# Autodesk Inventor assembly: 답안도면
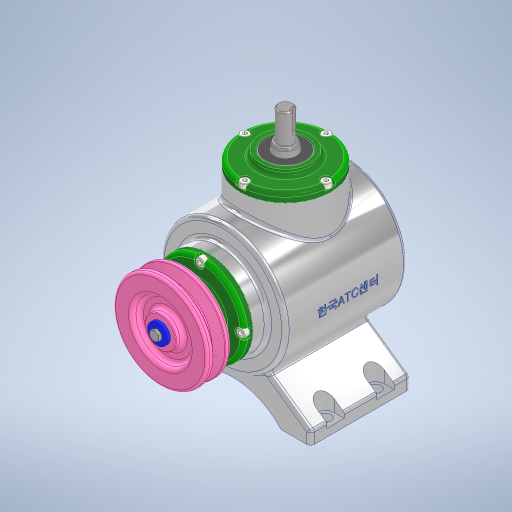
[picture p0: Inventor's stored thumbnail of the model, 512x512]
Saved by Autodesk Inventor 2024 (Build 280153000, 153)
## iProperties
Created: 2023-08
Part Number: 답안도면
Document SubType Name: Assembly
Designer: Owner
Author: Owner
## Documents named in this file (17)
- C:\Users\Owner\Desktop\730813V1006\답안조립품.iam
- C:\Users\Owner\Desktop\730813V1006\본체.ipt
- C:\Users\Owner\Desktop\730813V1006\V-벨트풀리.ipt
- C:\Users\Owner\Desktop\730813V1006\메인 베벨기어.ipt
- C:\Users\Owner\Desktop\730813V1006\메인 축.ipt
- 메인 축.ipt
- C:\Users\Owner\Desktop\730813V1006\베어링 6203.ipt
- C:\Users\Owner\Desktop\730813V1006\볼트 M4 x 10.ipt
- C:\Users\Owner\Desktop\730813V1006\서브 베벨기어.ipt
- C:\Users\Owner\Desktop\730813V1006\서브 축.ipt
- 서브 축.ipt
- C:\Users\Owner\Desktop\730813V1006\오일실 17 x 32 x 8.ipt
- C:\Users\Owner\Desktop\730813V1006\와셔 4 x 16.ipt
- C:\Users\Owner\Desktop\730813V1006\육각볼트 M4 x 8.ipt
- C:\Users\Owner\Desktop\730813V1006\커버.ipt
- C:\Users\Owner\Desktop\730813V1006\키 4 x 4 x 14.ipt
- C:\Users\Owner\Desktop\730813V1006\키 5 x 5 x 14.ipt
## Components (1 placed, 1 different names)
1. V-벨트풀리:1
